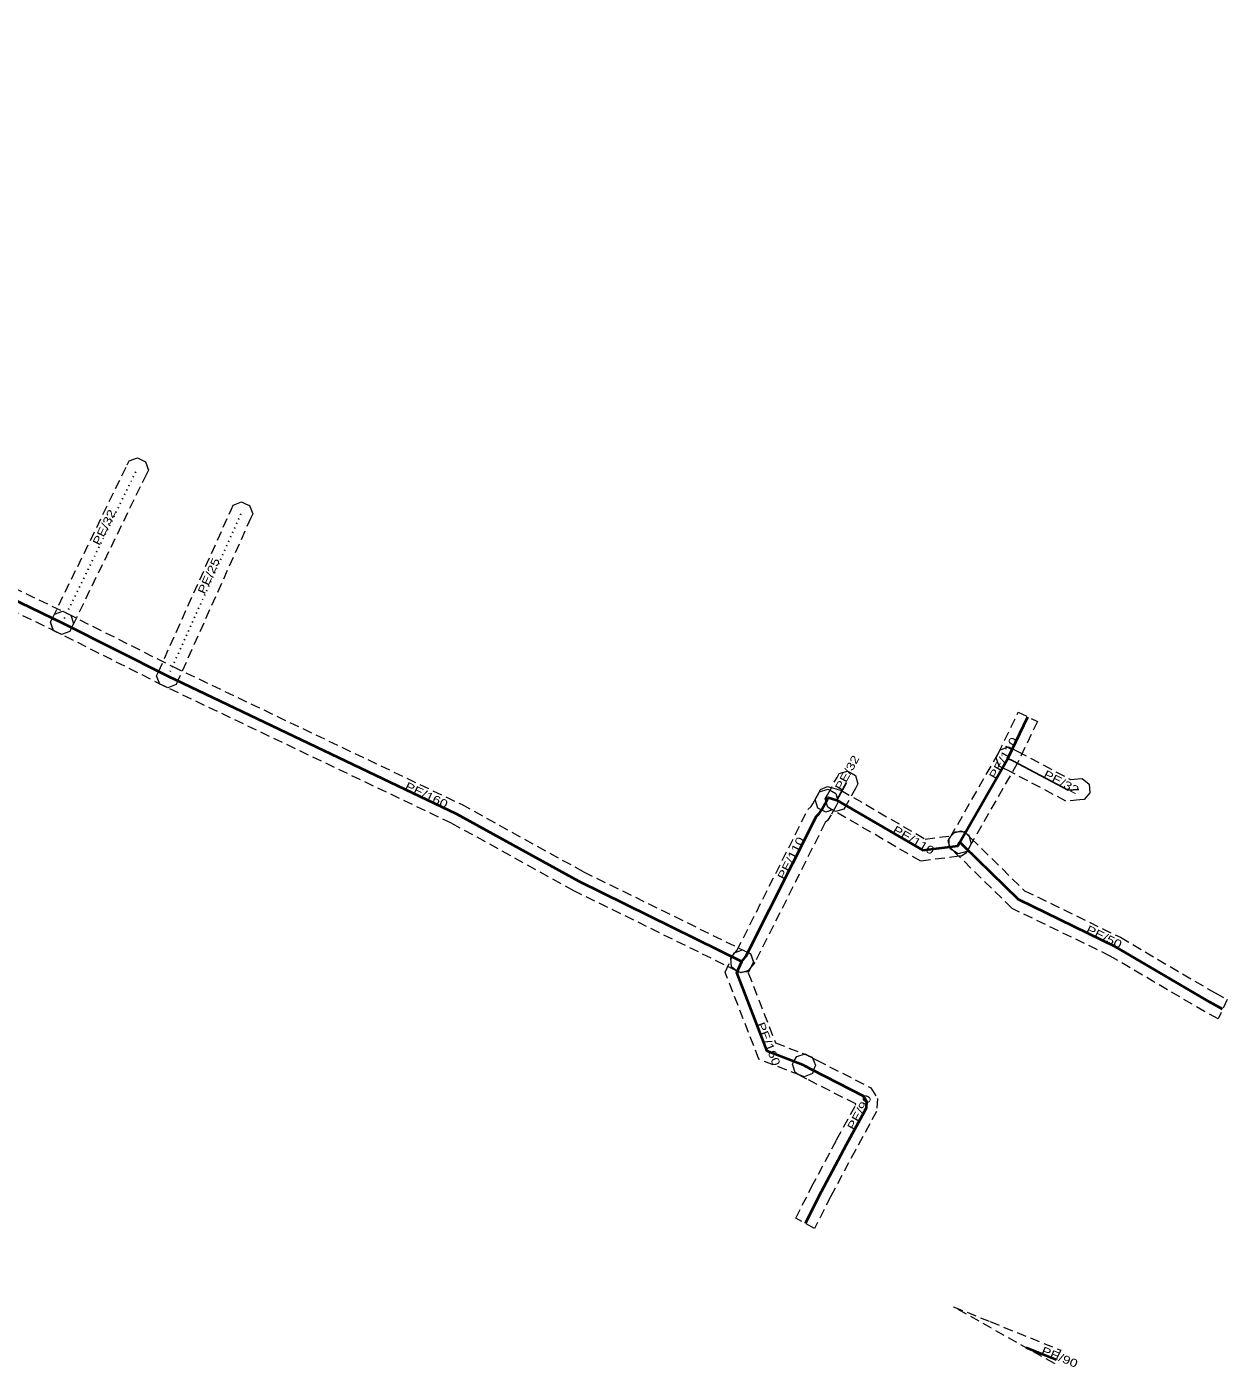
# Model space of a CAD drawing. Extents: x -757978 to -757756, y -1040973 to -1040847.
# Drawn here: x -757868.2 to -757755.7, y -1040973 to -1040847.4 of the extents above; entities that cross this region are included whole.
import ezdxf

# ---------------------------------------------------------------- set-up
doc = ezdxf.new("R2010")
doc.units = 0
doc.header["$LTSCALE"] = 0.3
doc.linetypes.add('DOTTED', pattern=[1.5, 0.3, -1.2])
doc.linetypes.add('MEDIUM_DASHED', pattern=[4.5, 3, -1.5])
for name, color, linetype, lineweight in [('1', 7, 'MEDIUM_DASHED', 13), ('24', 7, 'Continuous', 40), ('28', 7, 'DOTTED', 25)]:
    doc.layers.add(name, color=color, linetype=linetype, lineweight=lineweight)
doc.layers.add('30', color=7, linetype='Continuous')

msp = doc.modelspace()

# ---------------------------------------------------------------- linework, layer by layer
at = {"layer": '1'}
for points in [[(-757962.349, -1040856.396), (-757977.956, -1040849.138), (-757977.028, -1040847.364), (-757961.479, -1040854.594), (-757942.46, -1040864.124), (-757926.045, -1040872.227), (-757905.943, -1040882.234), (-757864.458, -1040902.317), (-757864.085, -1040902.498), (-757863.813, -1040903.28), (-757863.994, -1040903.653), (-757864.175, -1040904.026), (-757864.957, -1040904.298), (-757865.33, -1040904.117), (-757906.825, -1040884.03), (-757926.933, -1040874.019), (-757943.35, -1040865.914)], [(-757865.974, -1040903.151), (-757865.793, -1040902.779), (-757858.778, -1040888.399), (-757858.596, -1040888.027), (-757857.813, -1040887.757), (-757857.441, -1040887.938), (-757857.069, -1040888.12), (-757856.799, -1040888.903), (-757856.98, -1040889.275), (-757863.995, -1040903.655), (-757864.177, -1040904.027), (-757864.96, -1040904.297), (-757865.332, -1040904.116), (-757865.704, -1040903.934)], [(-757856.03, -1040908.183), (-757855.86, -1040907.805), (-757849.024, -1040892.568), (-757848.855, -1040892.19), (-757848.081, -1040891.895), (-757847.703, -1040892.065), (-757847.325, -1040892.234), (-757847.03, -1040893.008), (-757847.2, -1040893.386), (-757854.036, -1040908.623), (-757854.205, -1040909.001), (-757854.979, -1040909.296), (-757855.357, -1040909.126), (-757855.735, -1040908.957)], [(-757864.815, -1040902.137), (-757864.445, -1040902.323), (-757854.508, -1040907.316), (-757827.47, -1040920.223), (-757816.018, -1040926.549), (-757800.753, -1040934.057), (-757800.381, -1040934.24), (-757800.114, -1040935.023), (-757800.297, -1040935.395), (-757800.48, -1040935.767), (-757801.263, -1040936.034), (-757801.635, -1040935.851), (-757816.944, -1040928.323), (-757828.386, -1040922.003), (-757855.388, -1040909.112), (-757865.343, -1040904.111), (-757865.713, -1040903.925), (-757865.974, -1040903.138), (-757865.788, -1040902.768), (-757865.602, -1040902.398)], [(-757775.289, -1040911.588), (-757773.489, -1040912.458), (-757775.389, -1040916.392), (-757779.903, -1040924.28), (-757780.109, -1040924.64), (-757780.908, -1040924.857), (-757781.268, -1040924.651), (-757781.628, -1040924.445), (-757781.845, -1040923.646), (-757781.639, -1040923.286), (-757777.159, -1040915.46)], [(-757769.119, -1040919.784), (-757769.532, -1040919.819), (-757770.826, -1040919.929), (-757776.238, -1040917.053), (-757776.707, -1040916.827), (-757777.08, -1040916.648), (-757777.354, -1040915.866), (-757777.175, -1040915.493), (-757776.996, -1040915.12), (-757776.214, -1040914.846), (-757775.841, -1040915.025), (-757775.336, -1040915.267), (-757770.408, -1040917.887), (-757769.702, -1040917.827), (-757769.289, -1040917.792), (-757768.656, -1040918.325), (-757768.621, -1040918.738), (-757768.586, -1040919.151)], [(-757790.324, -1040918.309), (-757790.524, -1040918.672), (-757791.425, -1040920.311), (-757791.624, -1040920.674), (-757792.42, -1040920.905), (-757792.783, -1040920.705), (-757793.146, -1040920.506), (-757793.377, -1040919.71), (-757793.177, -1040919.347), (-757792.276, -1040917.708), (-757792.077, -1040917.345), (-757791.281, -1040917.114), (-757790.918, -1040917.314), (-757790.555, -1040917.513)], [(-757802.228, -1040934.635), (-757801.964, -1040934.316), (-757801.652, -1040933.94), (-757795.003, -1040920.708), (-757794.711, -1040920.442), (-757794.545, -1040920.192), (-757794.119, -1040919.407), (-757793.922, -1040919.042), (-757793.128, -1040918.806), (-757792.764, -1040919.004), (-757792.399, -1040919.201), (-757792.163, -1040919.995), (-757792.361, -1040920.359), (-757792.829, -1040921.224), (-757793.181, -1040921.754), (-757793.383, -1040921.938), (-757799.968, -1040935.042), (-757800.424, -1040935.592), (-757800.689, -1040935.911), (-757801.513, -1040935.988), (-757801.832, -1040935.724), (-757802.151, -1040935.459)], [(-757784.434, -1040925.554), (-757792.693, -1040920.758), (-757793.334, -1040920.961), (-757793.701, -1040920.77), (-757794.068, -1040920.579), (-757794.318, -1040919.789), (-757794.127, -1040919.422), (-757793.981, -1040919.141), (-757793.817, -1040918.825), (-757793.162, -1040918.543), (-757792.819, -1040918.641), (-757791.906, -1040918.902), (-757784.014, -1040923.486), (-757781.579, -1040923.18), (-757781.435, -1040922.927), (-757780.635, -1040922.709), (-757780.275, -1040922.914), (-757779.915, -1040923.119), (-757779.697, -1040923.919), (-757779.902, -1040924.279), (-757780.088, -1040924.605), (-757780.205, -1040924.81), (-757780.598, -1040925.072), (-757780.832, -1040925.101)], [(-757755.713, -1040938.513), (-757756.571, -1040940.322), (-757757.824, -1040939.652), (-757766.666, -1040934.452), (-757775.867, -1040929.976), (-757781.1, -1040924.855), (-757781.465, -1040924.503), (-757781.763, -1040924.215), (-757781.778, -1040923.387), (-757781.491, -1040923.089), (-757781.203, -1040922.791), (-757780.375, -1040922.776), (-757780.077, -1040923.063), (-757779.706, -1040923.421), (-757774.701, -1040928.32), (-757765.72, -1040932.688), (-757756.846, -1040937.908)], [(-757795.343, -1040945.773), (-757795.729, -1040945.623), (-757799.595, -1040944.117), (-757802.762, -1040935.953), (-757802.101, -1040934.532), (-757801.926, -1040934.156), (-757801.147, -1040933.872), (-757800.772, -1040934.047), (-757800.396, -1040934.222), (-757800.112, -1040935.001), (-757800.287, -1040935.376), (-757800.59, -1040936.025), (-757798.049, -1040942.573), (-757795.003, -1040943.759), (-757794.617, -1040943.909), (-757794.284, -1040944.668), (-757794.434, -1040945.054), (-757794.584, -1040945.44)], [(-757794.392, -1040959.988), (-757796.137, -1040959.006), (-757794.652, -1040956.08), (-757792.313, -1040951.676), (-757790.532, -1040948.428), (-757790.524, -1040948.309), (-757795.103, -1040945.973), (-757795.844, -1040945.569), (-757796.208, -1040945.371), (-757796.442, -1040944.577), (-757796.244, -1040944.213), (-757796.046, -1040943.849), (-757795.252, -1040943.615), (-757794.888, -1040943.813), (-757794.171, -1040944.203), (-757789.107, -1040946.787), (-757788.487, -1040947.799), (-757788.564, -1040949), (-757790.553, -1040952.626), (-757792.876, -1040957.002)], [(-757771.905, -1040972.643), (-757781.346, -1040967.33), (-757777.909, -1040968.707), (-757771.312, -1040971.393)]]:
    msp.add_lwpolyline(points, close=True, dxfattribs=at)
at = {"layer": '24', "lineweight": 25}
msp.add_line((-757791.4, -1040918.19), (-757792.301, -1040919.829), dxfattribs=at)
at = {"layer": '24'}
msp.add_line((-757771.741, -1040972.297), (-757774.555, -1040971.152), dxfattribs=at)
for points in [[(-757977.492, -1040848.251), (-757961.914, -1040855.495), (-757942.905, -1040865.019), (-757926.489, -1040873.123), (-757906.384, -1040883.132), (-757864.894, -1040903.217)], [(-757864.894, -1040903.217), (-757854.948, -1040908.214), (-757827.928, -1040921.113), (-757816.481, -1040927.436), (-757801.194, -1040934.954)], [(-757780.771, -1040923.783), (-757776.274, -1040915.926), (-757774.389, -1040912.023)], [(-757801.194, -1040934.954), (-757800.81, -1040934.491), (-757794.193, -1040921.323), (-757793.946, -1040921.098), (-757793.687, -1040920.708), (-757793.24, -1040919.883)], [(-757793.24, -1040919.883), (-757793.094, -1040919.602), (-757792.301, -1040919.829), (-757784.224, -1040924.52), (-757780.957, -1040924.109), (-757780.771, -1040923.783)], [(-757756.142, -1040939.417), (-757757.335, -1040938.78), (-757766.193, -1040933.57), (-757775.284, -1040929.148), (-757780.403, -1040924.138), (-757780.771, -1040923.783)], [(-757795.366, -1040944.691), (-757798.822, -1040943.345), (-757801.676, -1040935.989), (-757801.194, -1040934.954)], [(-757795.366, -1040944.691), (-757794.637, -1040945.088), (-757789.812, -1040947.55), (-757789.505, -1040948.051), (-757789.548, -1040948.714), (-757791.433, -1040952.151), (-757793.764, -1040956.541), (-757795.265, -1040959.497)]]:
    msp.add_lwpolyline(points, dxfattribs=at)
at = {"layer": '24', "lineweight": 25}
msp.add_lwpolyline([(-757769.617, -1040918.823), (-757770.617, -1040918.908), (-757775.787, -1040916.16), (-757776.274, -1040915.926)], dxfattribs=at)
at = {"layer": '28'}
for p, q in [((-757864.894, -1040903.217), (-757857.879, -1040888.837)), ((-757854.948, -1040908.214), (-757848.112, -1040892.977))]:
    msp.add_line(p, q, dxfattribs=at)

# ---------------------------------------------------------------- texts
at = {"layer": '30', "width": 1.3}
for s, rotation, p in [('PE/32', 63.995, (-757861.387, -1040896.027)), ('PE/25', 65.837, (-757851.53, -1040900.595)), ('PE/110', 60.215, (-757777.421, -1040917.93)), ('PE/32', 61.201, (-757791.851, -1040919.009)), ('PE/32', 332.008, (-757772.997, -1040917.643)), ('PE/160', 334.481, (-757832.828, -1040918.774)), ('PE/110', 329.853, (-757787.127, -1040922.834)), ('PE/110', 63.32, (-757797.224, -1040927.353)), ('PE/50', 334.061, (-757769.005, -1040932.202)), ('PE/160', 291.205, (-757799.803, -1040940.817)), ('PE/90', 61.258, (-757790.704, -1040950.821)), ('PE/90', 337.848, (-757773.194, -1040971.705))]:
    msp.add_text(s, height=0.75, rotation=rotation, dxfattribs=at).set_placement(p)

doc.saveas('drawing.dxf')
